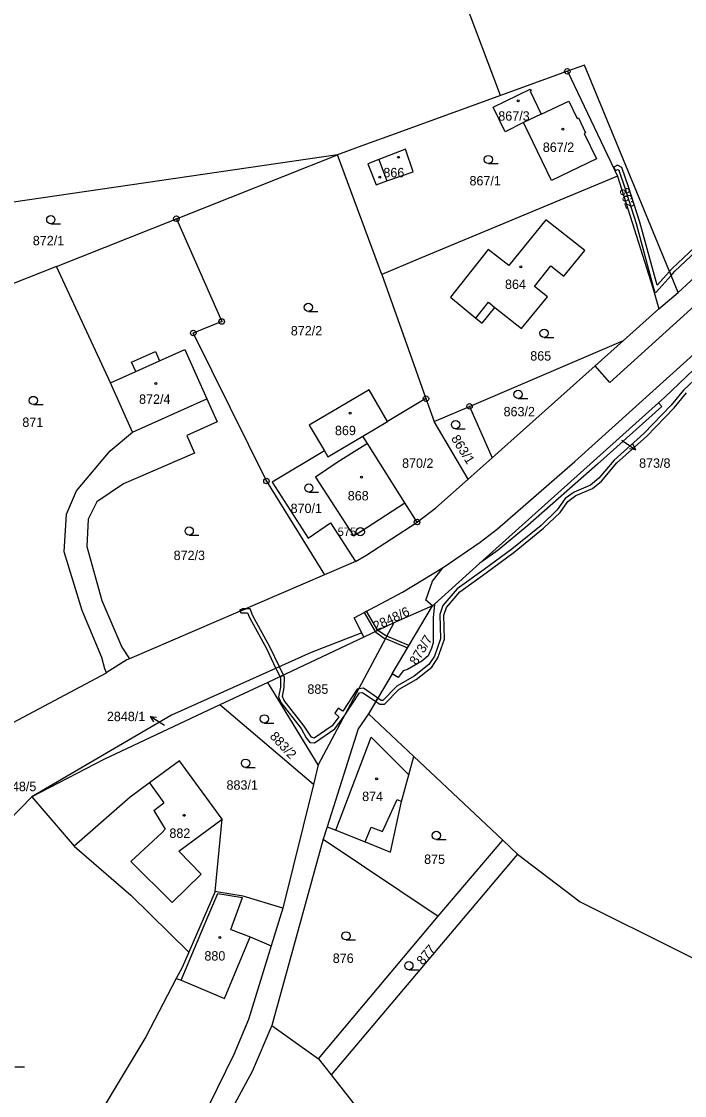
# Model space of a CAD drawing. Extents: x -562167 to -556918, y -1077891 to -1070763.
# Drawn here: x -558964.6 to -558844.3, y -1074571 to -1074376.3 of the extents above; entities that cross this region are included whole.
import ezdxf

# ---------------------------------------------------------------- set-up
doc = ezdxf.new("R2010")
doc.units = 0
for name, color, linetype in [('Hranice parcel', 7, 'Continuous'), ('Parcelní čísla', 7, 'Continuous'), ('Pop  PČ popisy', 7, 'Continuous'), ('Vnitřní kresba', 7, 'Continuous'), ('Věcná břemena k části', 7, 'Continuous'), ('Značky bodu BP', 7, 'Continuous'), ('Značky budov', 7, 'Continuous'), ('Značky kultur', 7, 'Continuous')]:
    doc.layers.add(name, color=color, linetype=linetype)

msp = doc.modelspace()

# ---------------------------------------------------------------- linework, layer by layer
at = {"layer": 'Hranice parcel'}
for p, q in [((-558877.7, -1074389.74), (-558940.76, -1074222.44)), ((-558865.55, -1074385.33), (-558877.7, -1074389.74)), ((-558865.55, -1074385.33), (-558856.48, -1074404.34)), ((-558870.32, -1074393.09), (-558873.48, -1074394.59)), ((-558907.23, -1074400.45), (-558979.2, -1074410.98)), ((-558936.46, -1074412.05), (-558907.23, -1074400.45)), ((-558899.22, -1074422.15), (-558907.23, -1074400.45)), ((-558958.19, -1074420.68), (-558936.46, -1074412.05)), ((-558958.19, -1074420.68), (-558977.25, -1074428.25)), ((-558948.43, -1074441.8), (-558958.19, -1074420.68)), ((-558848.95, -1074428.41), (-558845.48, -1074425.45)), ((-558855.39, -1074434.15), (-558848.95, -1074428.41)), ((-558883.29, -1074446.06), (-558855.39, -1074434.15)), ((-558855.39, -1074434.15), (-558860.53, -1074438.74)), ((-558860.53, -1074438.74), (-558879.22, -1074455.39)), ((-558891.2, -1074444.66), (-558898.16, -1074448.79)), ((-558891.2, -1074444.66), (-558889.72, -1074448.81)), ((-558889.72, -1074448.81), (-558883.29, -1074446.06)), ((-558883.29, -1074446.06), (-558879.22, -1074455.39)), ((-558881.4, -1074474.48), (-558849.01, -1074445.4)), ((-558902.65, -1074451.46), (-558898.16, -1074448.79)), ((-558883.52, -1074459.23), (-558889.72, -1074448.81)), ((-558901.82, -1074452.77), (-558902.65, -1074451.46)), ((-558895, -1074463.57), (-558901.82, -1074452.77)), ((-558879.22, -1074455.39), (-558883.52, -1074459.23)), ((-558892.81, -1074467.03), (-558895, -1074463.57)), ((-558903.95, -1074474.18), (-558909.63, -1074476.62)), ((-558881.4, -1074474.48), (-558889.67, -1074481.89)), ((-558909.63, -1074476.62), (-558944.97, -1074491.8)), ((-558890.03, -1074482.22), (-558889.67, -1074481.89)), ((-558897.34, -1074494.56), (-558890.03, -1074482.22)), ((-558890.03, -1074482.22), (-558897.04, -1074485.29)), ((-558897.04, -1074485.29), (-558910.72, -1074511.01)), ((-558897.04, -1074485.29), (-558902.44, -1074487.86)), ((-558902.44, -1074487.86), (-558902.83, -1074487.1)), ((-558902.44, -1074487.86), (-558919.85, -1074496.13)), ((-558969.83, -1074505.36), (-558949.15, -1074494.33)), ((-558897.34, -1074494.56), (-558901.62, -1074501.78)), ((-558919.85, -1074496.13), (-558928.56, -1074500.15)), ((-558910.72, -1074511.01), (-558919.85, -1074496.13)), ((-558911.61, -1074514.59), (-558928.56, -1074500.15)), ((-558893.4, -1074509.51), (-558901.62, -1074501.78)), ((-558910.72, -1074511.01), (-558911.61, -1074514.59)), ((-558877.27, -1074524.68), (-558893.4, -1074509.51)), ((-558911.61, -1074514.59), (-558917.14, -1074536.98)), ((-558962.71, -1074516.84), (-558968.99, -1074523.3)), ((-558962.71, -1074516.84), (-558955, -1074525.74)), ((-558909.11, -1074522.24), (-558909.83, -1074524.5)), ((-558909.83, -1074524.5), (-558919.14, -1074558.27)), ((-558909.83, -1074524.5), (-558889.01, -1074538.45)), ((-558889.01, -1074538.45), (-558877.27, -1074524.68)), ((-558874.58, -1074527.21), (-558877.27, -1074524.68)), ((-558874.58, -1074527.21), (-558908.4, -1074567.22)), ((-558929.41, -1074533.98), (-558934.21, -1074544.95)), ((-558917.14, -1074536.98), (-558919.25, -1074543.81)), ((-558910.68, -1074564.3), (-558889.01, -1074538.45)), ((-558919.14, -1074558.27), (-558910.68, -1074564.3)), ((-558910.68, -1074564.3), (-558908.4, -1074567.22))]:
    msp.add_line(p, q, dxfattribs=at)
for points in [[(-558888.09, -1074475.29), (-558881.38, -1074470.67), (-558878.25, -1074468.23), (-558864.21, -1074456.05), (-558843.29, -1074437.23), (-558829.43, -1074424.45), (-558817.13, -1074412.6), (-558806.63, -1074401.66), (-558799.75, -1074392.75), (-558792.3, -1074381.31), (-558786.7, -1074371.43), (-558778.45, -1074356.21), (-558768.35, -1074338.42), (-558761.41, -1074327.18), (-558753.84, -1074316.54), (-558745.59, -1074306.46), (-558736.99, -1074296.98), (-558727.15, -1074287), (-558717.71, -1074278)], [(-558795.52, -1074373.51), (-558800.23, -1074381.29), (-558805.91, -1074389.5), (-558808.89, -1074393.53), (-558812.04, -1074397.44), (-558815.96, -1074401.93), (-558820.11, -1074406.31), (-558831.69, -1074417.63), (-558841.87, -1074427.32), (-558857.85, -1074441.72), (-558860.53, -1074438.74)], [(-558845.48, -1074425.45), (-558862.45, -1074384.2), (-558865.55, -1074385.33)], [(-558877.7, -1074389.74), (-558895.44, -1074396.21), (-558903.49, -1074399.11), (-558907.23, -1074400.45)], [(-558873.48, -1074394.59), (-558876.82, -1074396.28), (-558879, -1074391.81), (-558872.29, -1074388.56), (-558872.14, -1074388.87), (-558872.32, -1074388.96), (-558870.32, -1074393.09)], [(-558870.32, -1074393.09), (-558865.31, -1074390.72), (-558863.79, -1074393.89), (-558863.56, -1074393.78), (-558862.25, -1074396.51), (-558862.48, -1074396.62), (-558860.28, -1074401.2), (-558868.43, -1074405.14), (-558873.48, -1074394.59)], [(-558894.9, -1074399.44), (-558899.73, -1074401.34), (-558901.72, -1074402.12), (-558900.22, -1074405.88), (-558898.27, -1074405.2), (-558893.53, -1074403.53), (-558894.9, -1074399.44)], [(-558856.48, -1074404.34), (-558892.59, -1074419.39), (-558899.22, -1074422.15)], [(-558856.48, -1074404.34), (-558850.04, -1074424.57), (-558848.95, -1074428.41)], [(-558936.46, -1074412.05), (-558928.25, -1074430.68), (-558933.4, -1074432.77), (-558920.13, -1074459.6), (-558909.63, -1074476.62)], [(-558882.14, -1074430.06), (-558881.01, -1074430.96), (-558878.69, -1074428.11), (-558873.86, -1074431.94), (-558869.18, -1074426.18), (-558871.54, -1074424.35), (-558868.54, -1074420.61), (-558866.17, -1074422.46), (-558862.4, -1074417.81), (-558869.48, -1074412.25), (-558876.19, -1074420.54), (-558879.92, -1074417.63), (-558886.77, -1074426.29), (-558882.14, -1074430.06)], [(-558845.48, -1074425.45), (-558842.36, -1074422.6), (-558831.46, -1074413.08)], [(-558899.22, -1074422.15), (-558893.4, -1074438.48), (-558891.2, -1074444.66)], [(-558948.43, -1074441.8), (-558943.81, -1074439.73), (-558944.58, -1074438.04), (-558940.26, -1074436.11), (-558939.51, -1074437.8), (-558934.91, -1074435.74), (-558930.92, -1074444.67), (-558929.05, -1074448.87), (-558934.59, -1074451.35), (-558933.18, -1074454.54), (-558946.05, -1074460.12), (-558950.88, -1074463.37), (-558952.46, -1074466.53), (-558952.72, -1074471.46), (-558949.96, -1074481.22), (-558946.34, -1074489.68), (-558944.97, -1074491.8)], [(-558842.59, -1074439.39), (-558847.94, -1074444.44), (-558849.01, -1074445.4)], [(-558949.15, -1074494.33), (-558949.45, -1074493.63), (-558950.01, -1074491.6), (-558953.53, -1074483.03), (-558956.83, -1074472.45), (-558956.37, -1074465.61), (-558954.57, -1074461.36), (-558948.5, -1074454.13), (-558944.41, -1074450.72), (-558948.43, -1074441.8)], [(-558898.16, -1074448.79), (-558901.49, -1074443.04), (-558912.41, -1074449.49), (-558909.63, -1074454.13)], [(-558849.01, -1074445.4), (-558848.43, -1074446.06), (-558860.07, -1074456.56), (-558872.71, -1074467.62), (-558878.09, -1074472.09), (-558881.4, -1074474.48)], [(-558909.63, -1074454.13), (-558908.98, -1074455.21), (-558902.65, -1074451.46)], [(-558909.63, -1074454.13), (-558919.07, -1074459.81), (-558912.55, -1074469.96), (-558908.51, -1074467.16), (-558903.95, -1074474.18)], [(-558901.82, -1074452.77), (-558907.11, -1074456.1), (-558911.22, -1074458.9), (-558904.37, -1074469.51), (-558903.11, -1074468.78), (-558895, -1074463.57)], [(-558892.81, -1074467.03), (-558892.72, -1074466.97), (-558889.38, -1074464.46), (-558883.52, -1074459.23)], [(-558903.95, -1074474.18), (-558902.08, -1074473.06), (-558892.81, -1074467.03)], [(-558902.83, -1074487.1), (-558904.23, -1074484.38), (-558895.45, -1074479.75), (-558888.09, -1074475.29)], [(-558890.03, -1074482.22), (-558891.21, -1074481.19), (-558890.01, -1074477.75), (-558888.09, -1074475.29)], [(-558889.67, -1074481.89), (-558889.87, -1074484.41), (-558889.9, -1074488.91), (-558890.17, -1074489.91), (-558890.81, -1074491.25), (-558891.97, -1074492.23), (-558894.57, -1074493.72), (-558895.35, -1074494.01), (-558896.25, -1074495.2), (-558897.34, -1074494.56)], [(-558902.83, -1074487.1), (-558912.04, -1074490.69), (-558937.33, -1074502.02), (-558962.71, -1074516.84)], [(-558944.97, -1074491.8), (-558945.44, -1074492), (-558949.01, -1074494.26), (-558949.15, -1074494.33)], [(-558928.56, -1074500.15), (-558949.64, -1074510.07), (-558962.71, -1074516.84)], [(-558901.62, -1074501.78), (-558903.48, -1074504.53), (-558909.11, -1074522.24)], [(-558929.41, -1074533.98), (-558928.15, -1074520.87), (-558935.89, -1074510.3), (-558941.35, -1074514.3), (-558944.82, -1074516.9), (-558955, -1074525.74)], [(-558909.11, -1074522.24), (-558907.55, -1074522.89), (-558902.23, -1074525), (-558897.61, -1074526.83), (-558895.65, -1074517.65), (-558894.32, -1074512.83), (-558893.4, -1074509.51)], [(-558955, -1074525.74), (-558944.71, -1074534.62), (-558934.21, -1074544.95)], [(-558874.58, -1074527.21), (-558863.23, -1074535.84), (-558826.85, -1074553.95), (-558824.94, -1074555.12)], [(-558917.14, -1074536.98), (-558924.37, -1074534.85), (-558928.84, -1074534.08), (-558929.41, -1074533.98)], [(-558936.48, -1074549.76), (-558935.62, -1074550.06), (-558927.75, -1074553.35), (-558923.09, -1074542.2), (-558919.25, -1074543.81)], [(-558919.25, -1074543.81), (-558923.38, -1074557.16), (-558926.02, -1074563.55), (-558930.59, -1074572.74), (-558932.54, -1074576.44), (-558933.93, -1074579.39), (-558951.9, -1074609.42), (-558965.77, -1074630.03)], [(-558934.21, -1074544.95), (-558935.44, -1074547.77), (-558936.48, -1074549.76)], [(-558936.48, -1074549.76), (-558942.03, -1074560.3), (-558977.54, -1074619.27)], [(-558919.14, -1074558.27), (-558922.7, -1074566.58), (-558930.7, -1074581.37), (-558948.49, -1074611.49), (-558962.7, -1074632.34)], [(-558908.4, -1074567.22), (-558895.78, -1074583.32), (-558940.24, -1074634.39), (-558955.92, -1074636.05), (-558962.7, -1074632.34)]]:
    msp.add_lwpolyline(points, dxfattribs=at)
at = {"layer": 'Pop  PČ popisy'}
for p, q in [((-558855.75, -1074452.16), (-558855.64, -1074452.23)), ((-558855.64, -1074452.23), (-558853.15, -1074453.91)), ((-558853.15, -1074453.91), (-558854.26, -1074453.76)), ((-558853.15, -1074453.91), (-558853.7, -1074452.93)), ((-558938.64, -1074503.87), (-558941.19, -1074502.28)), ((-558941.19, -1074502.28), (-558940.07, -1074502.39)), ((-558941.19, -1074502.28), (-558940.6, -1074503.24))]:
    msp.add_line(p, q, dxfattribs=at)
at = {"layer": 'Vnitřní kresba'}
for p, q in [((-558899.73, -1074401.34), (-558898.27, -1074405.2)), ((-558882.14, -1074430.06), (-558879.84, -1074427.19)), ((-558879.84, -1074427.19), (-558878.69, -1074428.11)), ((-558943.81, -1074439.73), (-558939.51, -1074437.8)), ((-558944.41, -1074450.72), (-558930.92, -1074444.67)), ((-558907.55, -1074522.89), (-558901.11, -1074506.04)), ((-558901.11, -1074506.04), (-558894.32, -1074512.83)), ((-558941.35, -1074514.3), (-558938.75, -1074517.94)), ((-558940.58, -1074519.3), (-558938.75, -1074517.94)), ((-558899.08, -1074523.11), (-558896.4, -1074517.33)), ((-558896.4, -1074517.33), (-558895.65, -1074517.65)), ((-558940.58, -1074519.3), (-558938.48, -1074522.71)), ((-558939.07, -1074523.27), (-558938.48, -1074522.71)), ((-558936.04, -1074526.68), (-558928.15, -1074520.87)), ((-558902.23, -1074525), (-558901.15, -1074522.31)), ((-558901.15, -1074522.31), (-558899.08, -1074523.11)), ((-558944.71, -1074528.54), (-558939.07, -1074523.27)), ((-558936.04, -1074526.68), (-558931.99, -1074530.86)), ((-558944.71, -1074528.54), (-558937.21, -1074535.96)), ((-558937.21, -1074535.96), (-558931.99, -1074530.86)), ((-558930.92, -1074538.98), (-558928.96, -1074534.35)), ((-558928.96, -1074534.35), (-558924.45, -1074535.04)), ((-558926.6, -1074540.85), (-558924.45, -1074535.04)), ((-558933.68, -1074545.47), (-558930.92, -1074538.98)), ((-558926.6, -1074540.85), (-558923.09, -1074542.2)), ((-558935.62, -1074550.06), (-558933.68, -1074545.47))]:
    msp.add_line(p, q, dxfattribs=at)
at = {"layer": 'Věcná břemena k části'}
for points in [[(-558857.1, -1074402.68), (-558856.82, -1074403.32), (-558856.44, -1074403.12), (-558856.24, -1074403.23), (-558855.14, -1074406.48), (-558853.09, -1074412.89), (-558850.01, -1074424.41), (-558849.69, -1074425.44), (-558849.45, -1074425.37), (-558846.75, -1074422.37), (-558847.05, -1074421.64), (-558849.29, -1074424.09), (-558852.41, -1074412.69), (-558854.48, -1074406.26), (-558855.66, -1074402.75), (-558856.44, -1074402.32)], [(-558925.02, -1074482.98), (-558924.91, -1074483.19), (-558923.88, -1074482.74), (-558924.5, -1074482.74)], [(-558917.67, -1074495.1), (-558917.04, -1074494.8), (-558917.78, -1074493.26), (-558919.52, -1074489.64), (-558922.57, -1074484.01), (-558923.06, -1074482.74), (-558923.88, -1074482.74), (-558924.91, -1074483.19), (-558924.76, -1074483.49), (-558923.54, -1074483.46), (-558923.21, -1074484.31), (-558920.14, -1074489.96), (-558918.42, -1074493.55)], [(-558899.92, -1074486.66), (-558901.99, -1074483.2), (-558902.43, -1074483.43), (-558900.39, -1074486.88), (-558900.31, -1074487.01), (-558898.79, -1074488.04), (-558898.56, -1074488.14), (-558894.54, -1074489.84), (-558894.28, -1074489.4), (-558898.32, -1074487.7), (-558898.55, -1074487.6)], [(-558903.42, -1074497.28), (-558903.68, -1074497.32), (-558906.3, -1074501.28), (-558907.11, -1074500.76), (-558907.7, -1074501.65), (-558907.02, -1074502.35), (-558908.22, -1074503.98), (-558911.5, -1074506.22), (-558911.98, -1074505.99), (-558913.3, -1074504.04), (-558916.92, -1074499.36), (-558917.2, -1074498.65), (-558916.9, -1074497.03), (-558916.86, -1074495.17), (-558917.04, -1074494.8), (-558917.67, -1074495.1), (-558917.56, -1074495.33), (-558917.6, -1074496.95), (-558917.92, -1074498.71), (-558917.54, -1074499.7), (-558913.86, -1074504.46), (-558912.94, -1074506.13), (-558912.28, -1074506.96), (-558911.44, -1074507.02), (-558907.72, -1074504.5), (-558906.03, -1074502.19), (-558903.27, -1074497.96), (-558902.72, -1074497.89), (-558900.3, -1074499.55), (-558899.94, -1074498.95), (-558902.54, -1074497.15)]]:
    msp.add_lwpolyline(points, close=True, dxfattribs=at)
for points in [[(-558841.4, -1074416.25), (-558846.53, -1074421.07), (-558847.05, -1074421.64), (-558846.75, -1074422.37), (-558846.03, -1074421.57), (-558841.2, -1074417.02)], [(-558841.65, -1074440.47), (-558844.49, -1074443.11), (-558846.71, -1074445.84), (-558851.69, -1074451), (-558857.05, -1074455.78), (-558859.86, -1074459.09), (-558861.35, -1074460.36), (-558864.34, -1074461.6), (-558865.97, -1074462.77), (-558867.38, -1074464.83), (-558870.33, -1074467.64), (-558875.65, -1074471.92), (-558880.67, -1074475.64), (-558885.52, -1074479.14), (-558888.11, -1074482.17), (-558888.68, -1074483.78), (-558888.56, -1074488.16), (-558889.67, -1074491.32), (-558890.67, -1074492.83), (-558893.36, -1074494.97), (-558896.51, -1074496.76), (-558899.02, -1074499.35), (-558899.35, -1074499.36), (-558899.94, -1074498.95), (-558900.3, -1074499.55), (-558899.57, -1074500.06), (-558898.72, -1074500.05), (-558896.07, -1074497.32), (-558892.96, -1074495.55), (-558890.15, -1074493.31), (-558889.03, -1074491.64), (-558887.86, -1074488.26), (-558887.98, -1074483.9), (-558887.49, -1074482.53), (-558885.04, -1074479.66), (-558880.25, -1074476.2), (-558875.23, -1074472.48), (-558869.87, -1074468.16), (-558866.84, -1074465.29), (-558865.47, -1074463.27), (-558864, -1074462.22), (-558860.98, -1074460.96), (-558859.36, -1074459.59), (-558856.55, -1074456.27), (-558851.21, -1074451.5), (-558846.19, -1074446.3), (-558843.97, -1074443.59)]]:
    msp.add_lwpolyline(points, dxfattribs=at)
at = {"layer": 'Značky bodu BP'}
for centre, radius in [((-558865.55, -1074385.33), 0.5), ((-558865.55, -1074385.33), 0.0303), ((-558936.46, -1074412.05), 0.5), ((-558936.46, -1074412.05), 0.0303), ((-558928.25, -1074430.68), 0.5), ((-558928.25, -1074430.68), 0.0303), ((-558933.4, -1074432.77), 0.5), ((-558933.4, -1074432.77), 0.0303), ((-558891.2, -1074444.66), 0.5), ((-558891.2, -1074444.66), 0.0303), ((-558883.29, -1074446.06), 0.5), ((-558883.29, -1074446.06), 0.0303), ((-558920.13, -1074459.6), 0.5), ((-558920.13, -1074459.6), 0.0303), ((-558903.11, -1074468.78), 0.75), ((-558892.81, -1074467.03), 0.5), ((-558892.81, -1074467.03), 0.0303), ((-558903.11, -1074468.78), 0.03)]:
    msp.add_circle(centre, radius, dxfattribs=at)
at = {"layer": 'Značky budov'}
for centre in [(-558874.48, -1074390.67), (-558866.37, -1074395.82), (-558896.2, -1074400.92), (-558899.59, -1074404.52), (-558873.99, -1074420.77), (-558940.2, -1074441.9), (-558904.94, -1074447.3), (-558902.87, -1074458.87), (-558900.14, -1074513.54), (-558935.04, -1074520.18), (-558928.6, -1074542.31)]:
    msp.add_circle(centre, 0.175, dxfattribs=at)
at = {"layer": 'Značky kultur'}
for p, q in [((-558879.88, -1074402.07), (-558878.13, -1074402.07)), ((-558959.24, -1074412.98), (-558957.49, -1074412.98)), ((-558912.53, -1074428.86), (-558910.78, -1074428.86)), ((-558869.77, -1074433.56), (-558868.02, -1074433.56)), ((-558874.49, -1074444.64), (-558872.74, -1074444.64)), ((-558962.4, -1074445.74), (-558960.65, -1074445.74)), ((-558885.83, -1074450.12), (-558884.08, -1074450.12)), ((-558912.44, -1074461.61), (-558910.69, -1074461.61)), ((-558934.14, -1074469.39), (-558932.39, -1074469.39)), ((-558920.52, -1074503.45), (-558918.77, -1074503.45)), ((-558923.92, -1074511.48), (-558922.17, -1074511.48)), ((-558889.31, -1074524.57), (-558887.56, -1074524.57)), ((-558905.7, -1074542.77), (-558903.95, -1074542.77)), ((-558894.3, -1074548.17), (-558892.55, -1074548.17)), ((-558965.77, -1074565.75), (-558964.02, -1074565.75))]:
    msp.add_line(p, q, dxfattribs=at)
for centre in [(-558879.88, -1074401.32), (-558959.24, -1074412.23), (-558912.53, -1074428.11), (-558869.77, -1074432.81), (-558962.4, -1074444.99), (-558874.49, -1074443.89), (-558885.83, -1074449.37), (-558912.44, -1074460.86), (-558934.14, -1074468.64), (-558920.52, -1074502.7), (-558923.92, -1074510.73), (-558889.31, -1074523.82), (-558905.7, -1074542.02), (-558894.3, -1074547.42)]:
    msp.add_circle(centre, 0.75, dxfattribs=at)

# ---------------------------------------------------------------- texts
at = {"layer": 'Parcelní čísla'}
for s, p in [('867/3', (-558878.08, -1074394.28)), ('867/2', (-558870, -1074399.94)), ('866', (-558898.92, -1074404.54)), ('867/1', (-558883.3, -1074406.01)), ('872/1', (-558962.5, -1074416.86)), ('864', (-558876.86, -1074424.78)), ('872/2', (-558915.71, -1074433.2)), ('865', (-558872.28, -1074437.76)), ('872/4', (-558943.23, -1074445.6)), ('863/2', (-558877.12, -1074447.86)), ('871', (-558964.4, -1074449.78)), ('869', (-558907.7, -1074451.28)), ('870/2', (-558895.53, -1074457.2)), ('873/8', (-558852.54, -1074457.19)), ('868', (-558905.38, -1074463.1)), ('870/1', (-558915.75, -1074465.39)), ('872/3', (-558936.96, -1074473.91)), ('885', (-558912.7, -1074498.15)), ('2848/1', (-558949.07, -1074503.11)), ('2848/5', (-558968.82, -1074515.8)), ('883/1', (-558927.37, -1074515.53)), ('874', (-558902.77, -1074517.59)), ('882', (-558937.73, -1074524.26)), ('875', (-558891.53, -1074528.98)), ('880', (-558931.38, -1074546.5)), ('876', (-558908.1, -1074546.92))]:
    msp.add_text(s, height=1.7, dxfattribs=at).set_placement(p)
for s, rotation, p in [('862', 290, (-558856.16, -1074406.82)), ('863/1', 302, (-558886.71, -1074451.88)), ('2848/6', 25, (-558900.29, -1074486.77)), ('873/7', 59, (-558892.88, -1074493.05)), ('883/2', 313, (-558919.64, -1074505.96)), ('877', 50, (-558891.77, -1074547.44))]:
    msp.add_text(s, height=1.7, rotation=rotation, dxfattribs=at).set_placement(p)
at = {"layer": 'Značky bodu BP'}
msp.add_text('575', height=1.5, dxfattribs=at).set_placement((-558907.21, -1074469.53))

doc.saveas('drawing.dxf')
